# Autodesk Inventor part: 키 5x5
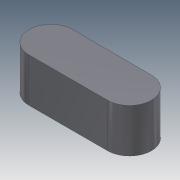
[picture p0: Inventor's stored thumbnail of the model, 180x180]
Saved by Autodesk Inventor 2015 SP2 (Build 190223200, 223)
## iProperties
Company: 한국ATC센터
Created: 2014-10
Part Number: 키 5x5
Document SubType Name: Modeling
Designer: KYOUNG IL JANG
Density: 7.85 g/cm^3
Mass: 2.53692 g
Surface Area: 2.9781 cm^2
Volume: 0.323175 cm^3
Material: 강철
Appearance: 강철 - 광택
Author: KYOUNG IL JANG
Revision Number: 1
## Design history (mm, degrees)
sketch "스케치1"
  geometry: L1 (-4.5, -2.5)-(4.5, -2.5); L2 (4.5, 2.5)-(-4.5, 2.5); A1 r 2.5 centre (4.5, 0) between (4.5, -2.5) and (4.5, 2.5); A2 r 2.5 centre (-4.5, 0) between (-4.5, 2.5) and (-4.5, -2.5); 2 further points
  constraints: 4 end point, 4 point on circle, 4 tangent, 2 centre point, 1 horizontal, 1 horizontal alignment, 1 midpoint, 1 parallel, 1 vertical alignment
  dimensions: "d0" = 5 distance between parallel lines of L1 L2; "d1" = 14 dimension on A1 A2
extrude "돌출1" new body sketch "스케치1" stored distance "d2" = 5; taper "d3" = 0 deg
node "솔리드1"
